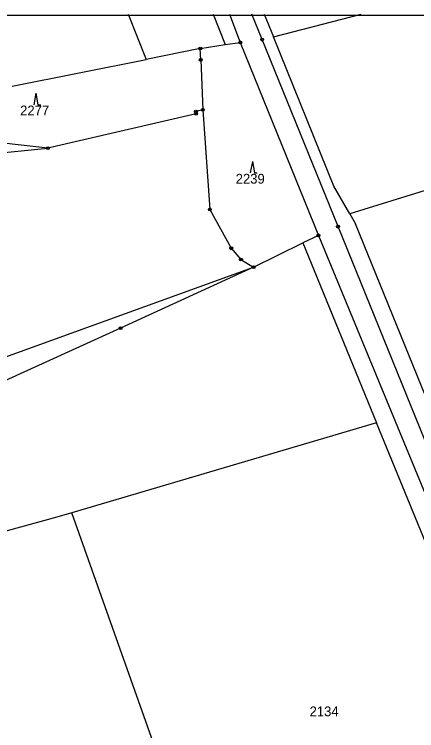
# Model space of a CAD drawing. Extents: x -566461 to -565198, y -1096301 to -1095707.
# Drawn here: x -566179.4 to -566039.2, y -1095956.2 to -1095706.8 of the extents above; entities that cross this region are included whole.
import ezdxf

# ---------------------------------------------------------------- set-up
doc = ezdxf.new("R2010")
doc.units = 0
for name, color, linetype in [('Vrstva 1', 7, 'Continuous'), ('Vrstva 18', 7, 'Continuous'), ('Vrstva 24', 7, 'Continuous'), ('Vrstva 25', 7, 'Continuous'), ('Vrstva 63', 7, 'Continuous')]:
    doc.layers.add(name, color=color, linetype=linetype)

msp = doc.modelspace()

# ---------------------------------------------------------------- linework, layer by layer
at = {"layer": 'Vrstva 1'}
for p, q in [((-566139.66, -1095706.75), (-566133.48, -1095722.43)), ((-566110.12, -1095706.75), (-566105.91, -1095717.31)), ((-566104.48, -1095706.75), (-566100.68, -1095716.51)), ((-566093.06, -1095715.54), (-566096.68, -1095706.75)), ((-566092.36, -1095706.75), (-566089.12, -1095714.61)), ((-566089.12, -1095714.61), (-566058.56, -1095706.75)), ((-566105.91, -1095717.31), (-566100.68, -1095716.51)), ((-566100.68, -1095716.51), (-566073.46, -1095783.73)), ((-566066.64, -1095780.66), (-566093.06, -1095715.54)), ((-566068.04, -1095766.58), (-566089.12, -1095714.61)), ((-566114.59, -1095718.64), (-566133.48, -1095722.43)), ((-566114.59, -1095718.64), (-566105.91, -1095717.31)), ((-566114.44, -1095722.62), (-566114.59, -1095718.64)), ((-566180.07, -1095731.78), (-566133.48, -1095722.43)), ((-566114.44, -1095722.62), (-566113.72, -1095739.97)), ((-566116.02, -1095741.42), (-566167.68, -1095753.36)), ((-566113.72, -1095739.97), (-566116.1, -1095740.64)), ((-566116.1, -1095740.64), (-566116.02, -1095741.42)), ((-566113.72, -1095739.97), (-566111.29, -1095774.66)), ((-566167.68, -1095753.36), (-566207.06, -1095748.95)), ((-566210.67, -1095757.54), (-566167.68, -1095753.36)), ((-565987.16, -1095752.85), (-566062.52, -1095776.24)), ((-566062.52, -1095776.24), (-566068.04, -1095766.58)), ((-566111.29, -1095774.66), (-566103.8, -1095788.22)), ((-566062.52, -1095776.24), (-566060.56, -1095779.67)), ((-565999.14, -1095946.93), (-566066.64, -1095780.66)), ((-566011.15, -1095901.4), (-566060.56, -1095779.67)), ((-566073.46, -1095783.73), (-566078.86, -1095786.37)), ((-566073.46, -1095783.73), (-566005.23, -1095949.18)), ((-566096.03, -1095794.77), (-566078.86, -1095786.37)), ((-566078.86, -1095786.37), (-566053.24, -1095848.98)), ((-566103.8, -1095788.22), (-566100.42, -1095792.14)), ((-566100.42, -1095792.14), (-566096.03, -1095794.77)), ((-566220.25, -1095839.74), (-566096.03, -1095794.77)), ((-566096.03, -1095794.77), (-566142.35, -1095816.04)), ((-566142.35, -1095816.04), (-566210.03, -1095846.72)), ((-566053.24, -1095848.98), (-566159.38, -1095880.28)), ((-565983.37, -1096019.72), (-566053.24, -1095848.98)), ((-566159.38, -1095880.28), (-566164.54, -1095881.8)), ((-566128.76, -1095966.51), (-566159.38, -1095880.28)), ((-566164.54, -1095881.8), (-566225.92, -1095898.77))]:
    msp.add_line(p, q, dxfattribs=at)
at = {"layer": 'Vrstva 24'}
for centre, radius in [((-566100.68, -1095716.51), 0.5), ((-566100.68, -1095716.51), 0.0327), ((-566093.06, -1095715.54), 0.5), ((-566093.06, -1095715.54), 0.0327), ((-566114.59, -1095718.64), 0.5), ((-566114.59, -1095718.64), 0.0327), ((-566114.44, -1095722.62), 0.5), ((-566114.44, -1095722.62), 0.0327), ((-566116.1, -1095740.64), 0.5), ((-566116.02, -1095741.42), 0.5), ((-566116.1, -1095740.64), 0.0327), ((-566116.02, -1095741.42), 0.0327), ((-566113.72, -1095739.97), 0.5), ((-566113.72, -1095739.97), 0.0327), ((-566167.68, -1095753.36), 0.5), ((-566167.68, -1095753.36), 0.0327), ((-566111.29, -1095774.66), 0.5), ((-566111.29, -1095774.66), 0.0327), ((-566066.64, -1095780.66), 0.5), ((-566066.64, -1095780.66), 0.0327), ((-566073.46, -1095783.73), 0.5), ((-566073.46, -1095783.73), 0.0327), ((-566103.8, -1095788.22), 0.5), ((-566103.8, -1095788.22), 0.0327), ((-566100.42, -1095792.14), 0.5), ((-566100.42, -1095792.14), 0.0327), ((-566096.03, -1095794.77), 0.5), ((-566096.03, -1095794.77), 0.0327), ((-566142.35, -1095816.04), 0.5), ((-566142.35, -1095816.04), 0.0327)]:
    msp.add_circle(centre, radius, dxfattribs=at)
at = {"layer": 'Vrstva 25'}
for p, q in [((-566171.87, -1095734.21), (-566172.6, -1095738.21)), ((-566171.87, -1095734.21), (-566171.14, -1095738.21)), ((-566171.14, -1095738.21), (-566170.14, -1095738.21)), ((-566096.47, -1095757.99), (-566097.2, -1095761.99)), ((-566096.47, -1095757.99), (-566095.74, -1095761.99)), ((-566095.74, -1095761.99), (-566094.74, -1095761.99))]:
    msp.add_line(p, q, dxfattribs=at)
at = {"layer": 'Vrstva 63'}
msp.add_line((-566458.38, -1095707.03), (-565198.38, -1095707.03), dxfattribs=at)

# ---------------------------------------------------------------- texts
at = {"layer": 'Vrstva 18'}
for s, p in [('2277', (-566177.33, -1095741.92)), ('2239', (-566102.27, -1095765.7)), ('2134', (-566076.53, -1095951.16))]:
    msp.add_text(s, height=3.4, dxfattribs=at).set_placement(p)

doc.saveas('drawing.dxf')
